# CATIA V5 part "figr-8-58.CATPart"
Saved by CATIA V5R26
Part number: Part1
Bounding box of the stored display mesh (mm): x -50.499 to 50.499, y -68.48 to 68.48, z -46 to 50
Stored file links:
  D:\_Deepak\CATIA\CATIA V5-6R2016_Deepak\Resources\Part files\Partfiles\c08_catia_v5_6r2016_prt\figr-8-58.CATPart
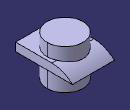
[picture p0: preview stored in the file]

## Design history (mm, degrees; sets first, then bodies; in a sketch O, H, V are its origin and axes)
Body1 (main body)
  Sketch1 on xy-plane, origin (0, 0, 0), H (1, 0, 0), V (0, 1, 0)
    line L1 (-50.499, 68.4797) -> (50.499, 68.4797)
    line L2 (50.499, 68.4797) -> (50.499, -68.4797)
    line L3 (50.499, -68.4797) -> (-50.499, -68.4797)
    line L4 (-50.499, -68.4797) -> (-50.499, 68.4797)
    axis line L5 (50.499, -68.4797) -> (-50.499, 68.4797)
    horizontal: L1 H, L3 H
    vertical: L2 V, L4 V
    midpoint: O L5
  Pad1: profile Sketch1, direction (0, 0, 1), length 20
  Fillet1: radius 71, on edge [face of Pad1 | face of Pad1]
  Body2
    Sketch2 on xy-plane, origin (0, 0, 0), H (1, 0, 0), V (0, 1, 0)
      circle A1 centre (0, 0) radius 43.2524
      point P1 (0, 43.2524)
      coincidence: A1 P1, P1 V
    Pad2: profile Sketch2, direction (0, 0, 1), length 50, opposite side length 46
  Assemble1: tool Body2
